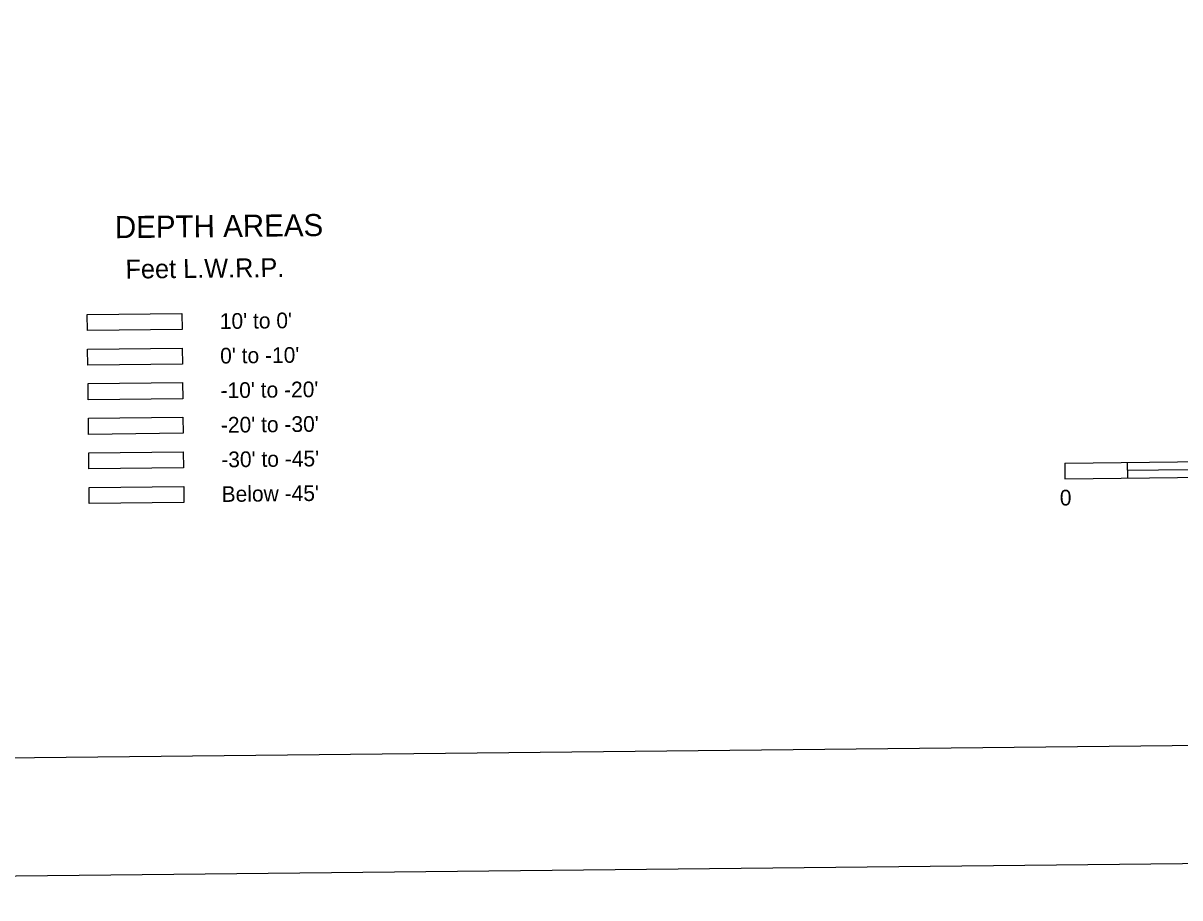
# Model space of a CAD drawing. Extents: x 3734862 to 3772949, y 391520 to 417239.
# Drawn here: x 3746739 to 3752854, y 392103 to 396730 of the extents above; entities that cross this region are included whole.
import ezdxf

# ---------------------------------------------------------------- set-up
doc = ezdxf.new("R2010")
doc.units = 0
for name, color, linetype in [('G-ANNO-NPLT', 7, 'Continuous'), ('V-ANNO-SYMB', 7, 'Continuous'), ('V-TOPO-DPTH', 7, 'Continuous')]:
    doc.layers.add(name, color=color, linetype=linetype)

msp = doc.modelspace()

# ---------------------------------------------------------------- linework, layer by layer
at = {"layer": 'G-ANNO-NPLT'}
msp.add_lwpolyline([(3735701, 392103.4), (3772365.6, 392490.7), (3772110.3, 416656), (3735445.7, 416268.7)], close=True, dxfattribs=at)
at = {"layer": 'V-ANNO-SYMB'}
for p, q in [((3752246, 394403.2), (3757525.7, 394458.9)), ((3752246, 394403.2), (3752246.9, 394320.2)), ((3752246.9, 394320.2), (3757526.6, 394375.9)), ((3752576, 394406.7), (3752576.9, 394323.7)), ((3752576.4, 394365.2), (3752906.4, 394368.6))]:
    msp.add_line(p, q, dxfattribs=at)
msp.add_lwpolyline([(3738444.4, 392757.5), (3771525.7, 393106.9), (3771283.7, 416022.2), (3738202.3, 415672.8), (3738444.4, 392757.5)], dxfattribs=at)
at = {"layer": 'V-TOPO-DPTH'}
for points in [[(3747078.4, 395188.8), (3747578.4, 395194.1), (3747579.3, 395109.1), (3747079.3, 395103.9)], [(3747080.3, 395005.9), (3747580.3, 395011.1), (3747581.2, 394926.1), (3747081.2, 394920.9)], [(3747082.3, 394822.9), (3747582.3, 394828.2), (3747583.1, 394743.2), (3747083.2, 394737.9)], [(3747084.2, 394639.9), (3747584.2, 394645.2), (3747585.1, 394560.2), (3747085.1, 394554.9)], [(3747086.1, 394456.9), (3747586.1, 394462.2), (3747587, 394377.2), (3747087, 394371.9)], [(3747088.1, 394273.9), (3747588.1, 394279.2), (3747588.9, 394194.2), (3747089, 394188.9)]]:
    msp.add_lwpolyline(points, close=True, dxfattribs=at)

# ---------------------------------------------------------------- texts
at = {"layer": 'V-ANNO-SYMB'}
msp.add_text('0', height=83, rotation=0.6052, dxfattribs=at).set_placement((3752220, 394178.4))
at = {"layer": 'V-TOPO-DPTH'}
for s, height, rotation, p in [('DEPTH AREAS', 116.7, 0.6052, (3747224.8, 395592.1)), ('Feet L.W.R.P.', 100, 0.60519, (3747280.8, 395378.5)), ("10' to 0'", 83, 0.60519, (3747779.3, 395112.2)), ("0' to -10'", 83, 0.60519, (3747781.2, 394929.3)), ("-10' to -20'", 83, 0.60519, (3747783.1, 394746.3)), ("-20' to -30'", 83, 0.60519, (3747785.1, 394563.3)), ("-30' to -45'", 83, 0.60519, (3747787, 394380.3)), ("Below -45'", 83, 0.60519, (3747788.9, 394197.3))]:
    msp.add_text(s, height=height, rotation=rotation, dxfattribs=at).set_placement(p)

doc.saveas('drawing.dxf')
